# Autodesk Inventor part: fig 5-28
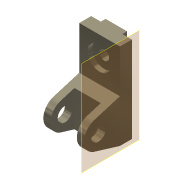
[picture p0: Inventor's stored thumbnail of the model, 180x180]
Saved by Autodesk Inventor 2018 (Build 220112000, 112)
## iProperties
Shininess: 65.0
Angle Display Precision: 2
Document Length Units: 11269
Document Angle Units: 11279
Document Time Units: 11290
Document Mass Units: 11283
Document Length Units Precision: 3
Document Angle Units Precision: 2
Created: 2001-11
Part Number: fig 5-28
Document SubType Name: Modeling
Designer: Renu Muthoo
Density: 1 g/cm^3
Material: Generic
Appearance: Metal-Titanium (Polished)
Density: 0.0
Volumn: 0.0
Area: 0.0
PropertySet Name: Model Information
Control State: 0
Master: False
Checked Out: False
Author: Renu Muthoo
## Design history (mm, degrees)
node "Sketch1"
sketch "Sketch2"
  geometry: L1 (33.257, 104.664)-(33.257, -75.336); L2 (33.257, -75.336)-(8.257, -75.336); L3 (8.257, -75.336)-(-45.451, -59.045); L4 (-45.451, -1.628)-(8.257, 14.664); L5 (8.257, 14.664)-(8.257, 104.664); L6 (8.257, 104.664)-(33.257, 104.664); C1 r 15 at (-36.743, -30.336); A1 r 30 centre (-36.743, -30.336) between (-45.451, -1.628) and (-45.451, -59.045)
  constraints: 12 end point, 2 centre point, 2 equal length, 2 parallel, 2 point on circle, 2 tangent, 1 coincident, 1 perpendicular, 1 vertical
  dimensions: "d0" = 180 distance of L1.start L1.end; "d1" = 30 radius of A1; "d2" = 25 distance of L5.end L1.start; "d3" = 45 distance from line of L2 A1.centre; "d4" = 70 distance from line of L1 A1.centre; "d5" = 30 diameter of C1
extrude "Extrusion1" new body sketch "Sketch2" distance "d6" = 85; taper "d7" = 0 deg
workplane "Work Plane1"
sketch "Sketch3"
  geometry: L1 (15, 62.364)-(70, 62.364); L2 (70, 62.364)-(70, -52.386); L3 (70, -52.386)-(15, -52.386); L4 (15, -52.386)-(15, 62.364); L5 (0, -45)-(0, -28.708) reference
  constraints: 8 end point, 2 parallel, 1 horizontal, 1 perpendicular
  dimensions: "d8" = 55 distance of L1.start L1.end; "d9" = 15 distance between parallel lines of L5 L4
extrude "Extrusion2" cut sketch "Sketch3" distance "d10" = 50; taper "d11" = 0 deg
sketch "Sketch4"
  geometry: L1 (0, 25)-(85, 25) reference; L2 (0, 0)-(0, 25) reference; L3 (20, 25)-(65, 25); L4 (65, 25)-(65, 35); L5 (65, 35)-(20, 35); L6 (20, 35)-(20, 25)
  constraints: 8 end point, 2 parallel, 1 horizontal, 1 perpendicular, 1 point on line
  dimensions: "d12" = 45 distance of L4.end L5.end; "d13" = 10 distance of L3.end L4.end; "d14" = 20 distance between parallel lines of L2 L6
extrude "Extrusion3" join sketch "Sketch4" stored distance "d15" = 50; taper "d16" = 0 deg
sketch "Sketch5"
  geometry: L1 (85, 0)-(85, 90) reference; L2 (0, 90)-(85, 90) reference; 1 further point
  dimensions: "d17" = 42 distance from line of L2 point (42.5, 48); "d18" = 42.5 distance from line of L1 point (42.5, 48)
hole "Hole1" sketch "Sketch5" at (42.5, 48) diameter "d19" = 20; stored, may be unused: countersink angle "d23" = 82 deg, drill point angle "d25" = 118 deg; dims "d20" = 6, "d21" = 50, "d22" = 10, "d24" = 8
workplane "Work Plane4"
body "Solid1"
other parameters: "d26" = 0
